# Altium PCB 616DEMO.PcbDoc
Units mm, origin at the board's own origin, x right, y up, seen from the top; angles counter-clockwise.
Board outline 70 x 50 mm, 2 copper layers (Top Layer, Bottom Layer), stack 0.527 mm thick; 70 components, 103 nets, 390 pads, 160 vias.
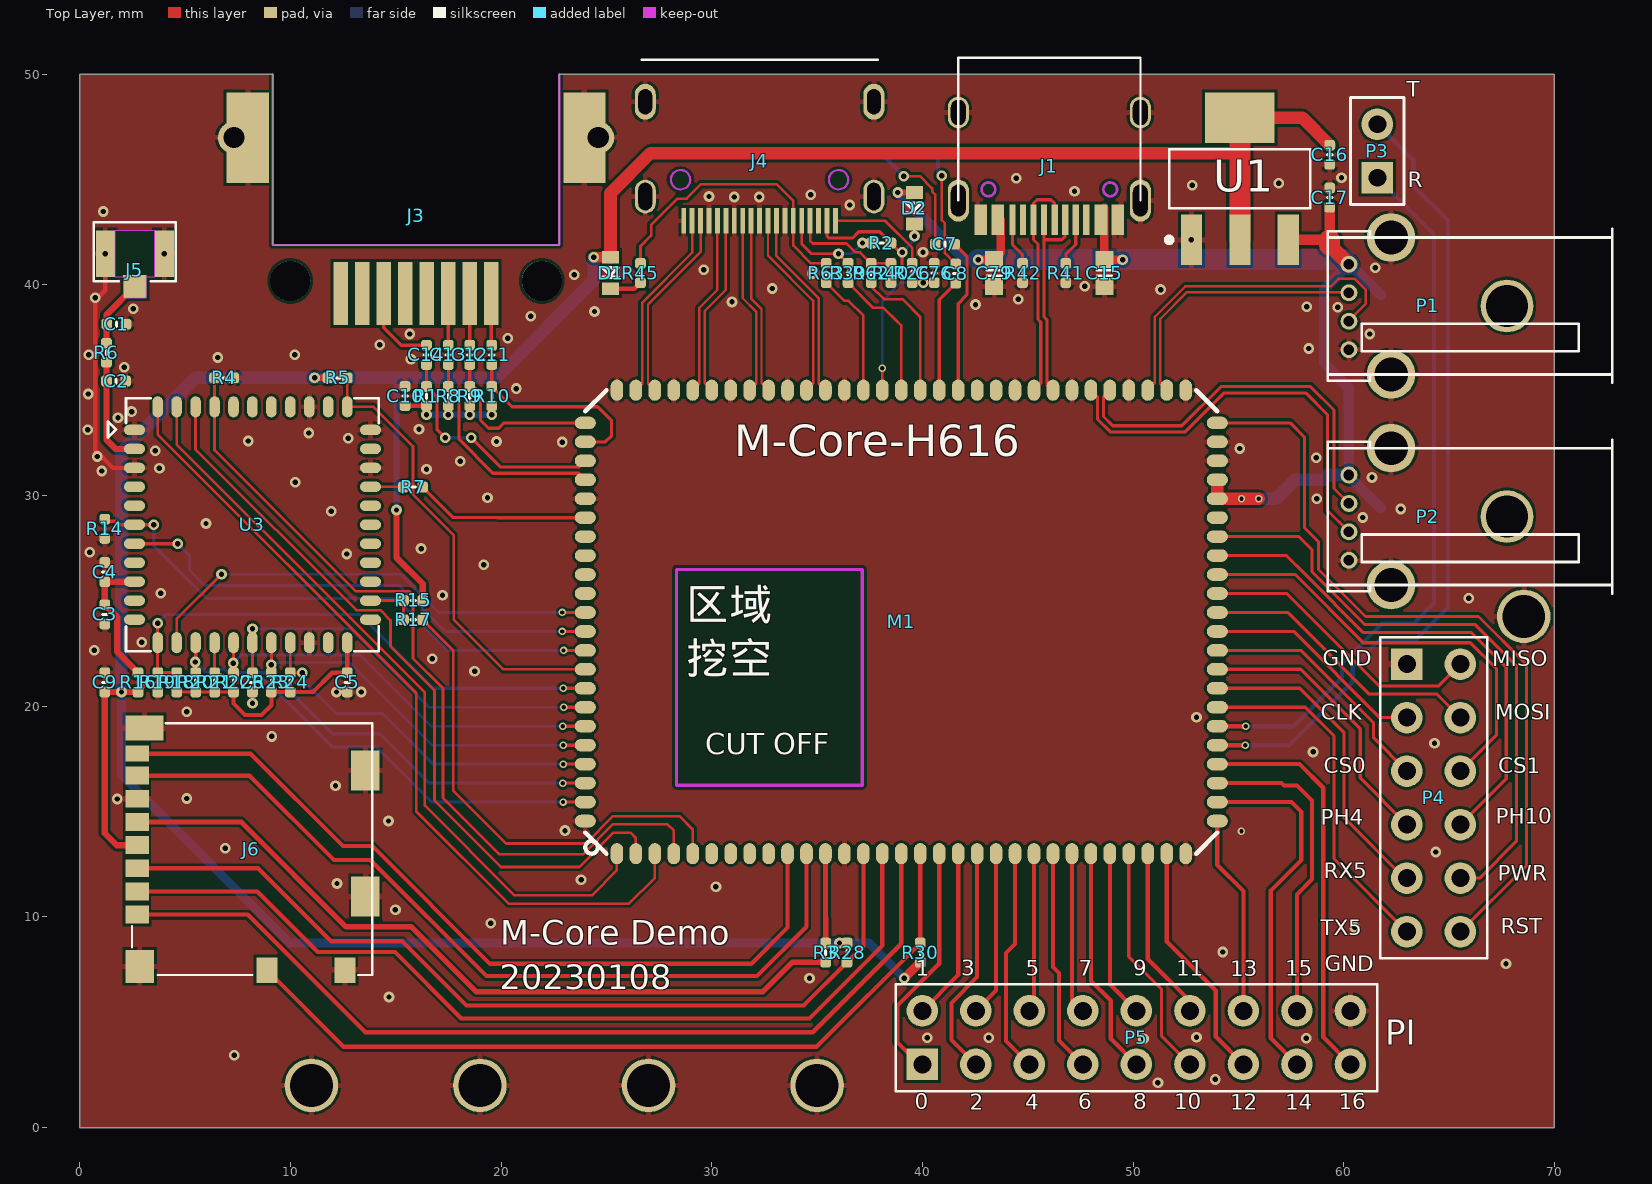
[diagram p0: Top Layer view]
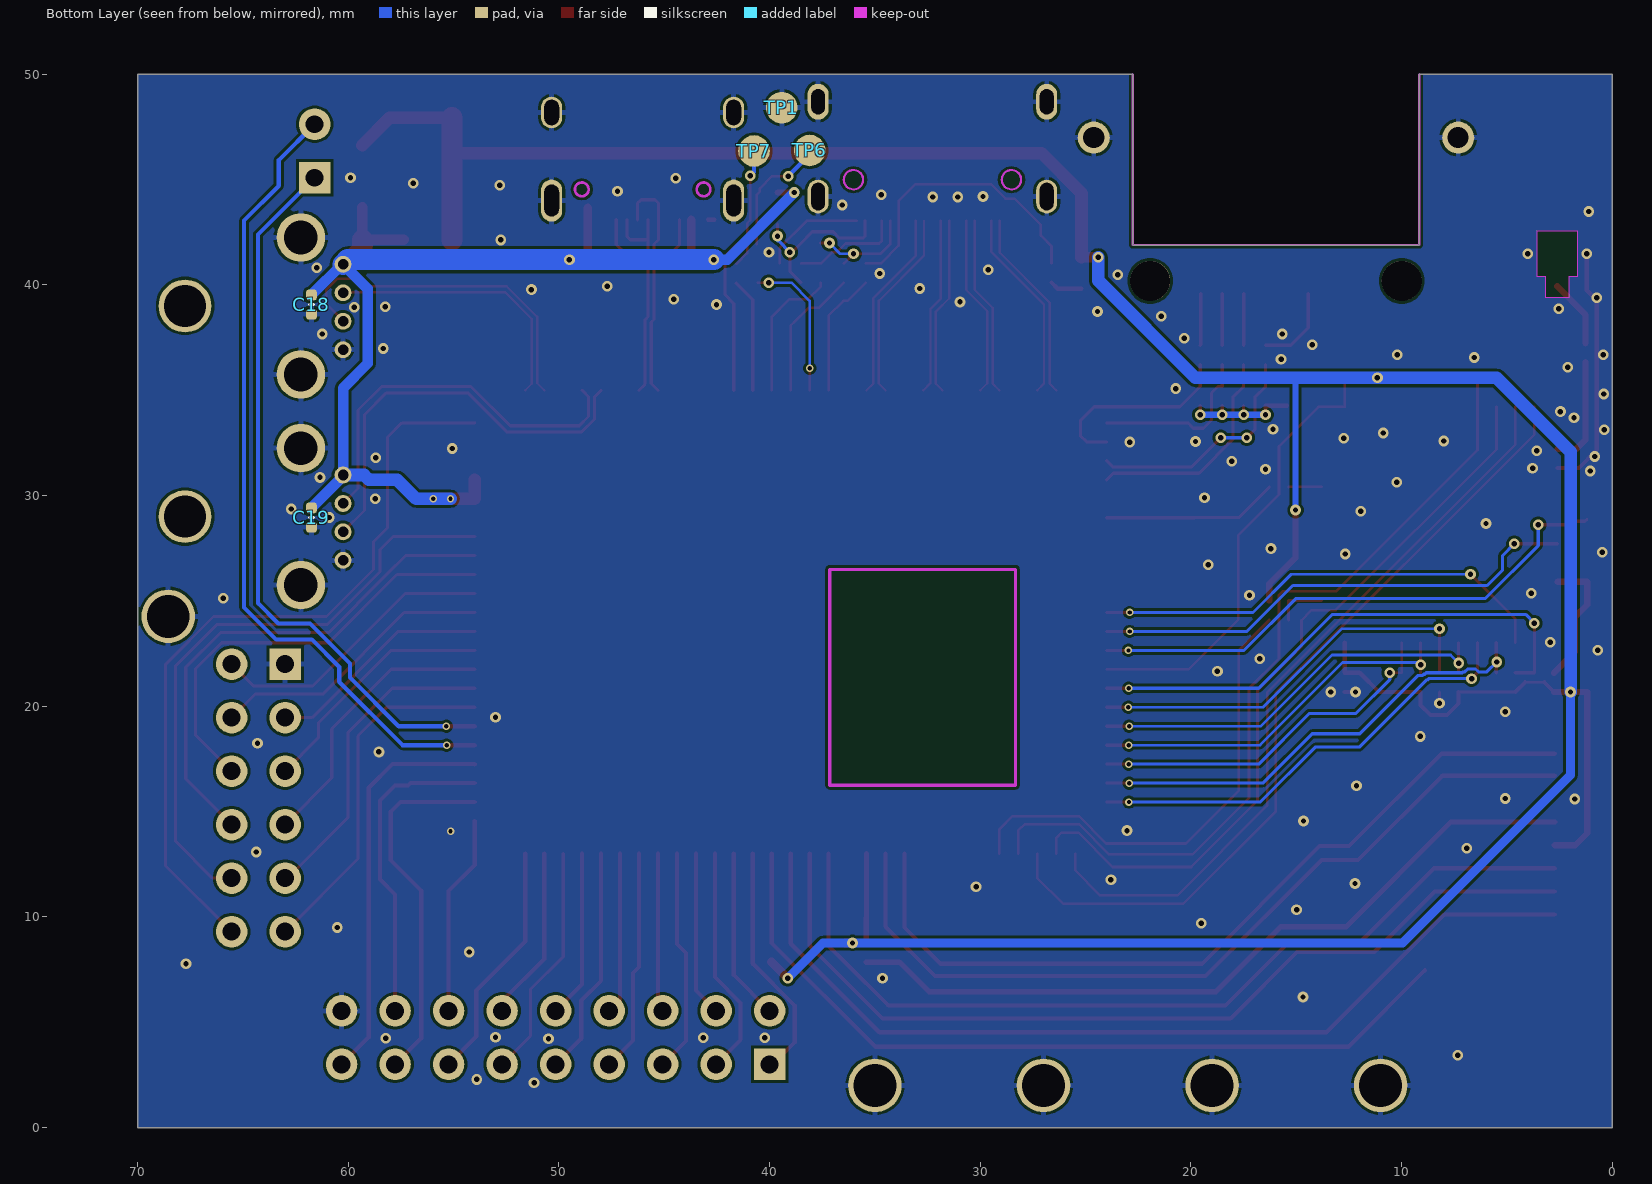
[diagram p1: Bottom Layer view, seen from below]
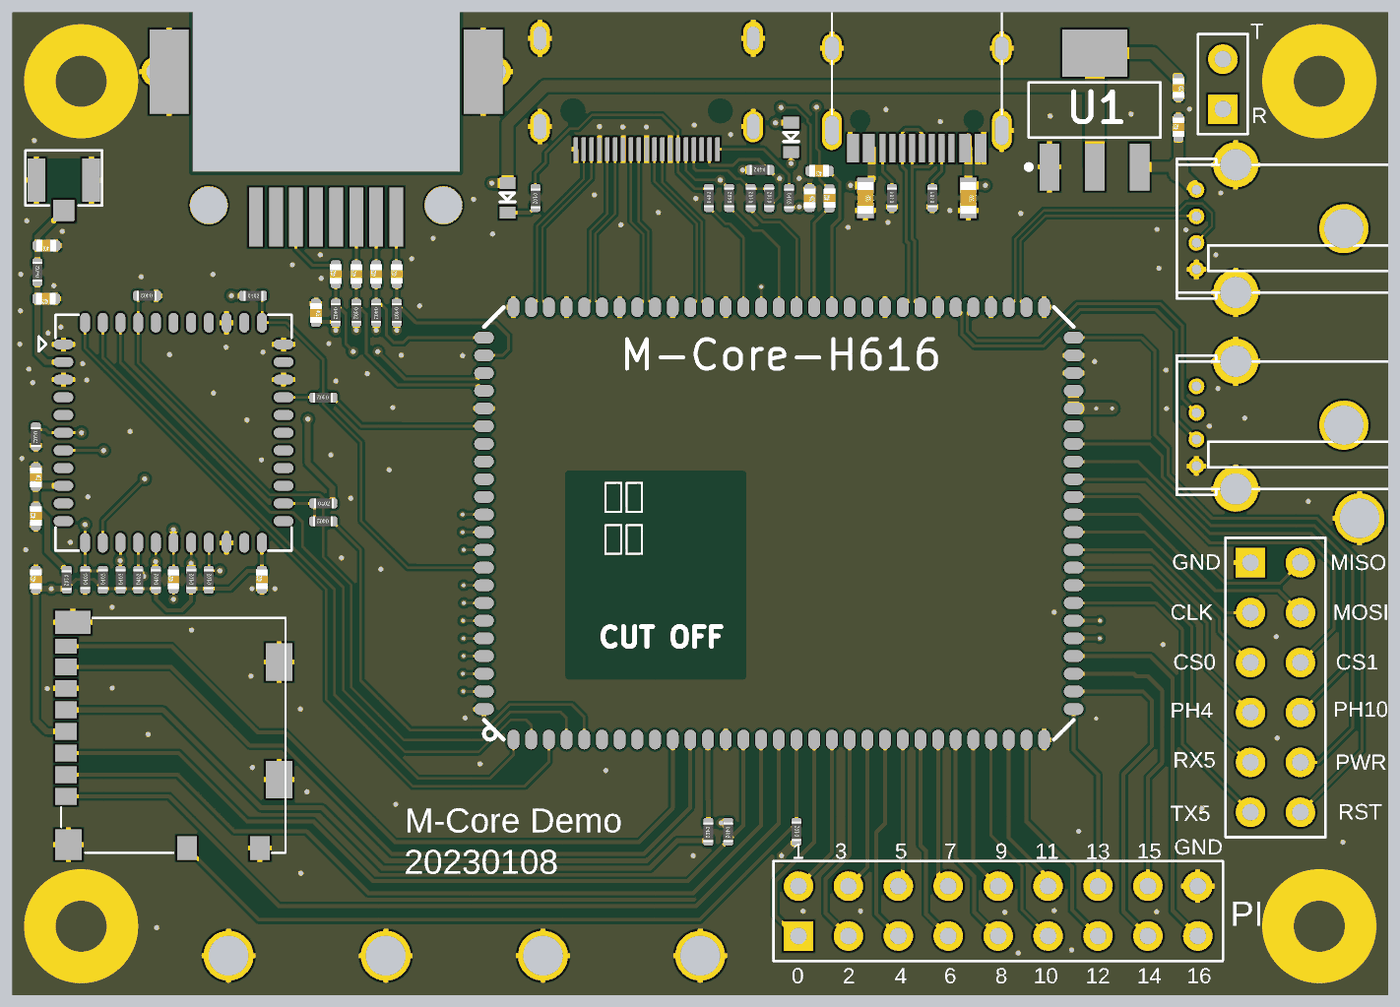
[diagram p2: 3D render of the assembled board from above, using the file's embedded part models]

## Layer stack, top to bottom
Top Solder: solder mask 0.0102, Solder Resist, Dk 3.5
Top Layer: signal copper 0.035
Dielectric2: prepreg 0.4572, PR-4, Dk 4.4
Bottom Layer: signal copper 0.035
Bottom Solder: solder mask 0.0102, Solder Resist, Dk 3.5

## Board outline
0,0 0,50 9.165,50 9.165,41.89 22.765,41.89 22.765,50 70.002,50 70.002,0

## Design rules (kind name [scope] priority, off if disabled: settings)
AssemblyTestPointUsage [All] p1 off:
AssemblyTestpoint [All] p1 off: testpointundercomponent=TRUE minsize=1.016 maxsize=2.54 preferedsize=1.524 minholesize=0 maxholesize=1.016 preferedholesize=0.813 testpointgrid=0.025 usegrid=TRUE gridtolerance=0 allowsidetop=TRUE allowsidebottom=TRUE
Clearance [All] p1: gap=0.127 ignorepadtopadclearanceinfootprint=FALSE
ComponentClearance [All] p1 off: gap=0.025 collisioncheckmode=3 verticalgap=0.025 showdistances=FALSE
DiffPairsRouting [All] p1: maxlimit=0.508 minlimit=0.14 mostfreqgap=0.178 toplayer_minwidth=0.102 toplayer_maxwidth=0.203 toplayer_prefwidth=0.117 bottomlayer_minwidth=0.102 bottomlayer_maxwidth=0.203 bottomlayer_prefwidth=0.117 maxuncoupledlength=76.2
FabricationTestPointUsage TestPointUsage [All] p1 off: valid=0 allowmultiple=FALSE
FabricationTestpoint Testpoint [(IsPad And (OnTopLayer Or OnBottomLayer))] p1 off: side=3 testpointundercomponent=TRUE minsize=1.016 maxsize=2.54 preferedsize=1.524 minholesize=0 maxholesize=1.016 preferedholesize=0.813 testpointgrid=0.025 allowsidetop=TRUE allowsidebottom=TRUE usegrid=TRUE gridtolerance=0
Height [All] p1 off: minheight=0 maxheight=25.4 prefheight=12.7
HoleSize [All] p1: absolutevalues=TRUE maxlimit=3.81 minlimit=0.025 maxpercent=80.000 minpercent=20.000
HoleToHoleClearance [All] p1: gap=0 allowstackedmicrovias=TRUE
MinimumSolderMaskSliver [All] p1 off: minsoldermaskwidth=0.025
NetAntennae [All] p1: netantennaetolerance=0.254
PlaneClearance [All] p1: clearance=0.127
PlaneConnect [All] p1: planeconnectstyle=Direct reliefexpansion=0.508 reliefentries=4 reliefconductorwidth=0.635 reliefairgap=0.254
PolygonConnect PolygonConnect_1 [All vs IsPad] p1: connectstyle=Relief reliefconductorwidth=0.254 reliefentries=4 polygonreliefangle="90 Angle" airgapwidth=0.127
PolygonConnect PolygonConnect_isvia [All vs IsVia] p2: connectstyle=Direct reliefconductorwidth=0.254 reliefentries=4 polygonreliefangle="90 Angle" airgapwidth=0.254
PolygonConnect [All] p3: connectstyle=Direct reliefconductorwidth=0.203 reliefentries=4 polygonreliefangle="90 Angle" airgapwidth=0.254
RoutingVias [All] p1: holewidth=0.203 width=0.406 viastyle="Through Hole" minholewidth=0.178 minwidth=0.356 maxholewidth=2.54 maxwidth=2.54
ShortCircuit [InNet('WIFI') vs InNet('GND')] p1 off: allowed=FALSE
SilkToSilkClearance [All] p1: silktosilkclearance=0
SilkToSolderMaskClearance SilkscreenOverComponentPads [IsPad] p1: minsilkscreentomaskgap=0 clearancetoexposedcopper=TRUE
SolderMaskExpansion [All] p1: expansion=0.102 istentingtop=FALSE
Width [All] p1: maxlimit=2.54 minlimit=0.12 preferedwidth=0.12
14 further rules are at their usual default settings.

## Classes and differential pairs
differential pair TXO: +TXO_P -TXO_N
differential pair RXI: +RXI_P -RXI_N
differential pair USB2: +USB2_P -USB2_N
differential pair USB1: +USB1_P -USB1_N
differential pair USB0: +USB0_P -USB0_N
differential pair HTXC: +HTXC_P -HTXC_N
differential pair HTX2: +HTX2_P -HTX2_N
differential pair HTX1: +HTX1_P -HTX1_N
differential pair HTX0: +HTX0_P -HTX0_N

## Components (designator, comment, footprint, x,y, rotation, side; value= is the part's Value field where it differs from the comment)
C1 "NC" C0402 1.742,38.137 r180 top
C2 "NC" C0402 1.727,35.433 r180 top
C3 "10uF" C0402 1.194,24.359 r90 top
C4 "0.1uF" C0402 1.194,26.365 r270 top
C5 "2.2uF" C0402 12.7,21.133 r90 top
C6 "NC" C0402 8.201,21.133 r90 top
C7 "10uF" C0402 41.072,41.935 r180 top
C8 "10uF" C0402 41.58,40.538 r90 top
C9 "0.1uF" C0402 1.194,21.133 r90 top
C10 "0.1uF" C0402 15.443,34.722 r270 top
C11 "0.1uF" C0402 19.558,36.678 r90 top
C12 "0.1uF" C0402 18.517,36.678 r90 top
C13 "0.1uF" C0402 17.501,36.678 r90 top
C14 "0.1uF" C0402 16.459,36.678 r90 top
C15 "47uF" C0603 48.641,40.564 r270 top
C16 "10uF" C0402 59.334,46.177 r270 top
C17 "10uF" C0402 59.334,44.145 r90 top
C18 "10uF" C0402 61.747,39.065 r270 bottom
C19 "10uF" C0402 61.747,28.956 r270 bottom
C76 "0.1uF" C0402 40.564,40.564 r270 top
C79 "47uF" C0603 43.409,40.564 r270 top
D1 "Diode" SOD523 25.197,40.564 r270 top
D2 "Diode" SOD523 39.624,43.637 r270 top
J1 "USB-TypeC-16P" USB-TYPEC-16P 46.027,45.636 r180 top locked
J3 "RJ45" RJ45 15.965,39.59 r180 top locked
J4 "HDMI_MINI" "HDMI_T _MINI" 32.273,43.043 r180 top locked
J5 "ipex" "I-PEX SOCKET" 2.616,41.478 r0 top
J6 "TF5033981892" TFCARD-1040310811 2.489,13.212 r270 top locked
M1 "MCore-H616" MCore-H616 39,24 r0 top locked
P1 "USB A RA STACKED" "USB-A STAND" 64,39 r270 top locked
P2 "USB A RA STACKED" "USB-A STAND" 64,29 r270 top locked
P3 "Header 2" HDR1X2 61.595,45.085 r90 top
P4 "Header 6X2" HDR2X6 63,22 r270 top locked
P5 "Header 9X2" HDR2X9 40,3 r0 top locked
R1 "50R" R0402 16.459,34.722 r270 top
R2 "1.8K" R0402 38.049,41.986 r180 top
R3 "33R" R0402 35.408,8.306 r270 top
R4 "NC/100K" R0402 6.858,35.585 r180 top
R5 "100K" R0402 12.243,35.585 r0 top
R6 "0R" R0402 1.27,36.779 r90 top
R7 "NC/0R" R0402 15.824,30.404 r180 top
R8 "50R" R0402 17.501,34.722 r270 top
R9 "50R" R0402 18.517,34.722 r270 top
R10 "50R" R0402 19.558,34.722 r270 top
R14 "NC/100K" R0402 1.194,28.423 r270 top
R15 "47K" R0402 15.824,25.019 r0 top
R16 "0R" R0402 2.769,21.133 r270 top
R17 "NC" R0402 15.824,24.105 r180 top
R18 "100K" R0402 4.607,21.133 r90 top
R19 "NC/100K" R0402 3.708,21.133 r90 top
R20 "47K" R0402 5.505,21.133 r90 top
R21 "47K" R0402 6.404,21.133 r90 top
R22 "47K" R0402 7.302,21.133 r90 top
R23 "47K" R0402 9.1,21.133 r90 top
R24 "47K" R0402 9.998,21.133 r90 top
R26 "1K" R0402 39.522,40.564 r270 top
R28 "10K" R0402 36.424,8.306 r270 top
R30 "10K" R0402 39.903,8.306 r90 top
R39 "100R" R0402 36.474,40.564 r90 top
R40 "1.8K" R0402 38.506,40.564 r90 top
R41 "5.1K" R0402 46.812,40.564 r90 top
R42 "5.1K" R0402 44.755,40.564 r90 top
R45 "27K 1%" R0402 26.619,40.564 r270 top
R62 "100R" R0402 37.567,40.564 r90 top
R63 "100R" R0402 35.433,40.564 r90 top
TP1 "TEST POINT" TEST-POINT1.5 39.421,48.412 r180 bottom
TP6 "TEST POINT" TEST-POINT1.5 38.1,46.38 r90 bottom
TP7 "TEST POINT" TEST-POINT1.5 40.742,46.355 r90 bottom
U1 "LM1117-3.3" SOT223-4N 55.067,45.034 r90 top
U3 "RTL8723DS" RTL8723DS 8.201,28.614 r0 top locked

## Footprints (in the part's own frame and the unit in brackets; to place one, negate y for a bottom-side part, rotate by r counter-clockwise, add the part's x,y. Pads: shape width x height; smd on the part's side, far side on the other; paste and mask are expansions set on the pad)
C0402 [mil]
  rrect50% 20x20 smd mask+2: 1(-18,0) 2(18,0)
  silkscreen extent 0,-4 0,4, body extent -19,-12 20,12, height 8
C0603 [mil]
  rect 31.5x33.46 smd: 1(-25,0) 2(25,0)
  silkscreen extent -5,-14 5,14, body extent -31,-16 32,16, height 12
"HDMI_T _MINI" [mm]
  rect 0.23x1.2 smd: 1(3.6,0) 2(3.2,0) 3(2.8,0) 4(2.4,0) 5(2,0) 6(1.6,0) 7(1.2,0) 8(0.8,0) 9(0.4,0) 10(0,0) 11(-0.4,0) 12(-0.8,0) 13(-1.2,0) 14(-1.6,0) 15(-2,0) 16(-2.4,0) 17(-2.8,0) 18(-3.2,0) 19(-3.6,0)
  oval 1x1.6 hole 0.65 slot 1.3 at 90 deg: 20(-5.425,-1.15) 23(5.425,-1.15)
  oval 1x1.7 hole 0.65 slot 1.2 at 90 deg: 21(-5.425,-5.65) 22(5.425,-5.65)
  Keep-Out Layer circle w0.1: c-3.75,-1.95 r0.46
  Keep-Out Layer circle w0.1: c3.75,-1.95 r0.46
  silkscreen extent -5.6,-7.65 5.6,-7.65
HDR1X2 [mm]
  rect 1.5x1.5 hole 0.85: 1(0,0)
  round 1.5 hole 0.85: 2(2.54,0)
  silkscreen extent -1.27,-1.27 3.81,1.27
HDR2X6 [mm]
  rect 1.5x1.5 hole 0.85: 1(0,0)
  round 1.5 hole 0.85: 2(0,2.54) 3(2.54,0) 4(2.54,2.54) 5(5.08,0) 6(5.08,2.54) 7(7.62,0) 8(7.62,2.54) 9(10.16,0) 10(10.16,2.54) 11(12.7,0) 12(12.7,2.54)
  silkscreen extent -1.27,-1.27 13.97,3.81
HDR2X9 [mm]
  rect 1.5x1.5 hole 0.85: 1(0,0)
  round 1.5 hole 0.85: 2(0,2.54) 3(2.54,0) 4(2.54,2.54) 5(5.08,0) 6(5.08,2.54) 7(7.62,0) 8(7.62,2.54) 9(10.16,0) 10(10.16,2.54) 11(12.7,0) 12(12.7,2.54) 13(15.24,0) 14(15.24,2.54) 15(17.78,0) 16(17.78,2.54) 17(20.32,0) 18(20.32,2.54)
  silkscreen extent -1.27,-1.27 21.59,3.81
"I-PEX SOCKET" [mm]
  rect 1.1x1.1 smd: 1(0,-1.55)
  rect 0.9x2.2 smd: 2(1.4,0) 3(-1.4,0)
  Keep-Out Layer pour cut-out: -0.95,1.1 -0.95,-1.101 -0.551,-1.101 -0.551,-2.101 0.001,-2.101 0.55,-2.101 0.55,-1.101 0.95,-1.101 0.95,1.1
  silkscreen extent -1.95,-1.3 1.95,1.5
MCore-H616 [mm]
  oval 0.6x1 smd mask+0.051: 1(-13.5,-11) 2(-12.6,-11) 3(-11.7,-11) 4(-10.8,-11) 5(-9.9,-11) 6(-9,-11) 7(-8.1,-11) 8(-7.2,-11) 9(-6.3,-11) 10(-5.4,-11) 11(-4.5,-11) 12(-3.6,-11) 13(-2.7,-11) 14(-1.8,-11) 15(-0.9,-11) 16(0,-11) 17(0.9,-11) 18(1.8,-11) 19(2.7,-11) 20(3.6,-11) 21(4.5,-11) 22(5.4,-11) 23(6.3,-11) 24(7.2,-11) 25(8.1,-11) 26(9,-11) 27(9.9,-11) 28(10.8,-11) 29(11.7,-11) 30(12.6,-11) 31(13.5,-11) 54(13.5,11) 55(12.6,11) 56(11.7,11) 57(10.8,11) 58(9.9,11) 59(9,11) 60(8.1,11) 61(7.2,11) 62(6.3,11) 63(5.4,11) 64(4.5,11) 65(3.6,11) 66(2.7,11) 67(1.8,11) 68(0.9,11) 69(0,11) 70(-0.9,11) 71(-1.8,11) 72(-2.7,11) 73(-3.6,11) 74(-4.5,11) 75(-5.4,11) 76(-6.3,11) 77(-7.2,11) 78(-8.1,11) 79(-9,11) 80(-9.9,11) 81(-10.8,11) 82(-11.7,11) 83(-12.6,11) 84(-13.5,11)
  oval 1x0.6 smd mask+0.051: 32(15,-9.45) 33(15,-8.55) 34(15,-7.65) 35(15,-6.75) 36(15,-5.85) 37(15,-4.95) 38(15,-4.05) 39(15,-3.15) 40(15,-2.25) 41(15,-1.35) 42(15,-0.45) 43(15,0.45) 44(15,1.35) 45(15,2.25) 46(15,3.15) 47(15,4.05) 48(15,4.95) 49(15,5.85) 50(15,6.75) 51(15,7.65) 52(15,8.55) 53(15,9.45) 85(-15,9.45) 86(-15,8.55) 87(-15,7.65) 88(-15,6.75) 89(-15,5.85) 90(-15,4.95) 91(-15,4.05) 92(-15,3.15) 93(-15,2.25) 94(-15,1.35) 95(-15,0.45) 96(-15,-0.45) 97(-15,-1.35) 98(-15,-2.25) 99(-15,-3.15) 100(-15,-4.05) 101(-15,-4.95) 102(-15,-5.85) 103(-15,-6.75) 104(-15,-7.65) 105(-15,-8.55) 106(-15,-9.45)
  Keep-Out Layer lines w0.152: -10.668,-7.747 -10.668,2.489 -1.854,2.489 -1.854,-7.747 -10.668,-7.747
  silkscreen extent -15,-11 15,11
R0402 [mil]
  rrect50% 20x20 smd mask+2: 1(-18,0) 2(18,0)
  silkscreen extent -4,0 4,0, body extent -19,-10 21,10, height 14
RJ45 [mm] "RJ45接口不带变压器H8.6"
  rect 0.7x3 smd: 1(-3.57,0) 2(-2.55,0) 3(-1.53,0) 4(-0.51,0) 5(0.51,0) 6(1.53,0) 7(2.55,0) 8(3.57,0)
  round 1.524 hole 1: 9(-8.65,-7.4) 10(8.65,-7.4)
  rect 2x4.3 smd: 9(-7.99,-7.4) 10(7.99,-7.4)
  round 1.9 hole 1.9: ""(-5.97,-0.6) ""(5.97,-0.6)
  Keep-Out Layer lines w0.1: 6.8,-10.4 6.8,-2.3 -6.8,-2.3 -6.8,-10.4
RTL8723DS [mm]
  oval 1x0.5 smd: 1(-5.6,4.5) 2(-5.6,3.6) 3(-5.6,2.7) 4(-5.6,1.8) 5(-5.6,0.9) 6(-5.6,0) 7(-5.6,-0.9) 8(-5.6,-1.8) 9(-5.6,-2.7) 10(-5.6,-3.6) 11(-5.6,-4.5) 23(5.6,-4.5) 24(5.6,-3.6) 25(5.6,-2.7) 26(5.6,-1.8) 27(5.6,-0.9) 28(5.6,0) 29(5.6,0.9) 30(5.6,1.8) 31(5.6,2.7) 32(5.6,3.6) 33(5.6,4.5)
  oval 0.5x1 smd: 12(-4.5,-5.6) 13(-3.6,-5.6) 14(-2.7,-5.6) 15(-1.8,-5.6) 16(-0.9,-5.6) 17(0,-5.6) 18(0.9,-5.6) 19(1.8,-5.6) 20(2.7,-5.6) 21(3.6,-5.6) 22(4.5,-5.6) 34(4.5,5.6) 35(3.6,5.6) 36(2.7,5.6) 37(1.8,5.6) 38(0.9,5.6) 39(0,5.6) 40(-0.9,5.6) 41(-1.8,5.6) 42(-2.7,5.6) 43(-3.6,5.6) 44(-4.5,5.6)
  silkscreen extent -6.86,-6 6,6, body extent -6,-6 6,6, height 1.6
SOD523 [mm]
  rect 0.6x0.8 smd: A(-0.75,0) K(0.75,0)
  silkscreen extent -0.25,-0.38 0.2,0.38
SOT223-4N [mm] "SOT223, 4-Leads, Body 6.5x3.5mm, Pitch 2.3mm, Lead Span 7mm, IPC Medium Density"
  rect 2.4x1 smd: 1(-2.9,2.3) 2(-2.9,0) 3(-2.9,-2.3)
  rect 2.4x3.3 smd: 4(2.9,0)
  silkscreen extent -3.02,-3.35 1.4,3.47, body extent -1.85,-3.35 1.85,3.35, height 1.7
TEST-POINT1.5 [mm]
  round 1.5 smd paste-0.4: 1(0,0)
TFCARD-1040310811 [mm] "TFCARD"
  rect 0.85x1.1 smd: 1(3.105,0.239) 2(2.005,0.239) 3(0.905,0.239) 4(-0.195,0.239) 5(-1.295,0.239) 6(-2.395,0.239) 7(-3.495,0.239)
  rect 0.75x1.1 smd: 8(-4.545,0.239)
  rect 1.55x1.35 smd: G1(5.565,0.365)
  rect 1.17x1.8 smd: G2(-5.755,0.59)
  rect 1.9x1.35 smd: G3(-3.73,11.075) G4(2.24,11.075)
  rect 1.2x1 smd: G5(5.74,10.1) G6(5.74,6.4)
  silkscreen extent -5.98,0 5.98,11.4
"USB-A STAND" [mm]
  round 0.8 hole 0.5: 1(-1.975,-3.75) 2(-0.625,-3.75) 3(0.725,-3.75) 4(2.075,-3.75)
  round 2.3 hole 1.6: 5(-3.25,-1.75) 6(3.25,-1.75)
  round 2.5 hole 2: 7(0,3.75)
  silkscreen extent -3.65,-4.75 3.65,8.75
USB-TYPEC-16P [mm]
  oval 1x1.5 hole 0.7 slot 1.2 at 90 deg: 0(-4.32,-2.548) 0(4.32,-2.548)
  oval 1x2 hole 0.7 slot 1.5 at 90 deg: 0(-4.32,1.632) 0(4.32,1.632)
  rect 0.3x1.45 smd: A1(-3.4,2.548) A4(-2.6,2.548) A5(-1.25,2.548) A6(-0.25,2.548) A7(0.25,2.548) A8(1.25,2.548) A9(2.6,2.548) A12(3.4,2.548) B1(3.1,2.548) B4(2.3,2.547) B5(1.75,2.548) B6(0.75,2.547) B7(-0.75,2.547) B8(-1.75,2.548) B9(-2.3,2.547) B12(-3.1,2.548)
  Keep-Out Layer circle w0.127: c2.89,1.103 r0.325
  Keep-Out Layer circle w0.127: c-2.89,1.103 r0.325
  silkscreen extent -4.33,-5.15 4.33,1.63

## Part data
C1 C2 C3 C4 C5 C6 C7 C8 C9 C10 C11 C12 C13 C14 C15 C16 C17 C18 C19 C76 C79: library part CAP, "普通小电容"
D1 D2: "普通二极管"
J3: "RJ45不带网络变压器"
J5: library part MCX_IPEX
P1 P2: library part "USB A Right Angle Stacked", "CONN RECEPT STACKED USB A RT ANG"
P3: "Header, 2-Pin"
P4: "Header, 6-Pin, Dual row"
P5: "Header, 9-Pin, Dual row"
R1 R2 R3 R4 R5 R6 R7 R8 R9 R10 R14 R15 R16 R17 R18 R19 R20 R21 R22 R23 R24 R26 R28 R30 R39 R40 R41 R42 R45 R62 R63: library part RES, "普通电阻"
TP1 TP6 TP7: library part TP, "Description"
U1: "800mA and 1A Low Dropout Positive Regulator 2.85V, 3.3V, 5V, and Adjustable", PackageDocument=revC
U3: library part AP6212

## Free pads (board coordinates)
  round 2.54 hole 2.032: 2(11,2) 2(27,2) 2(35,2) 2(68.547,24.264) ""(19,2)

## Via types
v1: diameter 0.508, hole 0.254, Top Layer to Bottom Layer, tented both sides, 144 vias
v2: diameter 0.356, hole 0.203, Top Layer to Bottom Layer, tented both sides, 16 vias

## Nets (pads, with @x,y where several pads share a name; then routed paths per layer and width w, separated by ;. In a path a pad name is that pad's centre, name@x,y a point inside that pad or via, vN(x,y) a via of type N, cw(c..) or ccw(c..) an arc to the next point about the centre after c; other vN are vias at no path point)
AP-CLK24M-OUT: M1.90 R7.1 | length 8.3
  Top Layer w0.152: R7.1 17.733,28.952 19.812,28.952 19.814,28.95 M1.90
AP-SDC1-CLK: C6.2 M1.100 U3.17 | length 19.4
  Top Layer w0.127: C6.2 U3.17 v1(8.201,23.676)
  Top Layer w0.15: v2(22.973,19.95) M1.100
  Bottom Layer w0.127: v1(8.201,23.676) 12.849,23.676 16.573,19.952 v2@22.958,19.952
AP-SDC1-CMD: M1.101 R22.2 U3.16 | length 19.7
  Top Layer w0.127: U3.16 7.301,21.592 R22.2
  Top Layer w0.15: v2(22.936,19.05) M1.101
  Bottom Layer w0.127: v1(7.29,22.047) 7.671,22.428 13.31,22.428 16.686,19.052 v2@22.958,19.052
AP-SDC1-D0: M1.102 R23.2 U3.18 | length 18
  Top Layer w0.127: R23.2 9.101,21.591 U3.18
  Top Layer w0.15: v2(22.951,18.15) M1.102
  Bottom Layer w0.127: v1(9.093,21.971) 9.195,22.073 12.802,22.073 16.722,18.152 v2@22.958,18.152
AP-SDC1-D1: M1.103 R24.2 U3.19 | length 17.4
  Top Layer w0.127: U3.19 10.001,21.593 v1(10.564,21.593)
  Top Layer w0.15: v2(22.958,17.25) M1.103
  Bottom Layer w0.15: v1(10.564,21.593) 10.564,21.263 12.167,19.66 14.376,19.66 16.784,17.252 v2(22.958,17.25)
AP-SDC1-D2: M1.104 R20.2 U3.14 | length 22.5
  Top Layer w0.15: U3.14 5.505,23.009 R20.2 ; v2(22.929,16.35) M1.104
  Bottom Layer w0.15: v1(5.486,22.098) 5.956,21.628 6.353,21.628 6.491,21.767 6.869,21.767 7.008,21.628 7.074,21.628 7.114,21.588 8.832,21.588 8.904,21.515 8.95,21.515 9.002,21.463 9.22,21.463 11.989,18.694 14.249,18.694 16.592,16.352 v2@22.958,16.352
AP-SDC1-D3: M1.105 R21.2 U3.15 | length 21.6
  Top Layer w0.15: U3.15 6.401,21.593 R21.2 6.404,21.587 v1(6.68,21.311) ; v2(22.943,15.45) M1.105
  Bottom Layer w0.15: v1(6.68,21.311) 8.717,21.311 8.79,21.238 8.836,21.238 12.014,18.059 14.097,18.059 16.705,15.452 v2@22.958,15.452
AP-UART1-CTS: M1.4 R4.2 U3.41 | length 39.8
  Top Layer w0.127: R4.2 U3.41 6.401,32.156 13.106,25.451 13.365,25.451 13.368,25.454 14.233,25.454 14.237,25.451 15.096,25.451 15.108,25.464 15.626,25.464 15.638,25.451 15.646,25.451 15.824,25.273 15.824,22.276 17.247,20.853 17.247,15.646 19.926,12.967 23.889,12.967 25.324,14.402 27.889,14.402 28.2,14.091 M1.4
AP-UART1-RTS: M1.3 U3.44 | length 39.1
  Top Layer w0.127: U3.44 3.701,32.901 15.977,20.625 15.977,15.011 20.371,10.617 26.06,10.617 27.3,11.857 M1.3
AP-UART1-RX: M1.2 U3.42 | length 36.4
  Top Layer w0.127: U3.42 5.501,32.193 13.132,24.562 14.275,24.562 14.757,24.079 14.757,22.835 16.84,20.752 16.84,15.519 19.99,12.37 23.724,12.37 25.349,13.995 26.137,13.995 26.4,13.732 M1.2
AP-UART1-TX: M1.1 U3.43 | length 36
  Top Layer w0.127: U3.43 4.601,32.432 12.827,24.206 16.383,20.65 16.383,15.291 20.65,11.024 24.308,11.024 25.5,12.216 M1.1
AP-WAKE-BT: M1.97 R14.1 U3.6 | length 25.9
  Top Layer w0.15: R14.1 1.295,28.778 1.676,28.778 1.841,28.614 U3.6 v1(3.517,28.614) ; v2(22.968,22.65) M1.97
  Bottom Layer w0.15: v1(3.517,28.614) 3.517,27.623 6.02,25.121 15.011,25.121 17.48,22.652 v2@22.911,22.652
BT-RESETN: M1.98 R5.2 U3.34 | length 21.5
  Top Layer w0.12: 20.537,21.752 20.538,21.75 M1.98
  Top Layer w0.127: U3.34@12.7,34.215 R5.2 ; U3.34 13.945,34.214 15.824,32.334 15.824,30.048 17.755,28.118 17.755,24.115 20.118,21.752 20.537,21.752
BT-WAKE-AP: M1.96 U3.7 | length 23.5
  Top Layer w0.15: U3.7 4.646,27.714 v1(4.648,27.711) ; v2(22.911,23.55) M1.96
  Bottom Layer w0.15: v1(4.648,27.711) 5.207,27.153 5.207,26.467 5.944,25.73 15.164,25.73 17.342,23.552 v2@22.911,23.552
CLK-FANOUT1: M1.5 R17.1 | length 23.1
  Top Layer w0.127: R17.1 17.729,22.657 17.729,16.002 20.244,13.487 24.028,13.487 25.324,14.783 28.473,14.783 29.1,14.156 M1.5
GND: C1.1 C2.1 C3.1 C4.1 C5.1 C6.1 C9.2 C10.1 C15.2 C16.2 C17.2 C18.2 C19.2 C76.1 C79.2 J1.0 J1.A1 J1.A12 J1.B1 J1.B12 J3.9 J3.10 J4.1 J4.4 J4.7 J4.10 J4.13 J4.20 J4.21 J4.22 J4.23 J5.2 J5.3 J6.6 J6.G1 J6.G2 J6.G3 J6.G4 J6.G5 M1.13 M1.31 M1.51 M1.52 M1.54 M1.57 M1.60 M1.63 M1.72 M1.75 M1.78 M1.81 M1.84 M1.89 M1.106 P1.4 P1.5 P1.6 P2.4 P2.5 P2.6 P4.1 P5.18 pad. pad.2 R4.1 R14.2 R19.1 R41.1 R42.1 TP1.1 U1.1 U3.1 U3.3 U3.20 U3.31 U3.33 U3.36 | length 13.1
  Top Layer w0.127: v1(8.201,20.139) C6.1
  Top Layer w0.2: v1(1.216,41.478) 1.216,39.748 0.737,39.268 0.737,32.156 1.579,31.314 U3.3 ; v1(12.192,20.676) C5.1 ; J1.A12 J1.B1
  other v1: 51.181,2.134 53.899,2.286 7.341,3.429 50.495,4.216 58.228,4.235 40.234,4.267 43.155,4.267 53.01,4.293 14.681,6.198 34.646,7.087 67.703,7.776 54.254,8.331 60.528,9.5 19.507,9.703 14.986,10.338 30.201,11.43 12.217,11.582 23.8,11.76 64.364,13.081 6.909,13.259 23.038,14.097 14.656,14.554 1.778,15.596 5.08,15.621 12.141,16.231 58.547,17.831 64.313,18.237 9.119,18.567 53.01,19.482 5.08,19.736 13.36,20.676 18.745,21.666 16.739,22.25 0.686,22.657 2.946,23.038 65.938,25.121 17.221,25.273 3.849,25.357 19.177,26.721 12.675,27.229 0.483,27.305 16.205,27.483 5.994,28.677 60.909,28.956 11.938,29.261 62.713,29.362 58.725,29.845 19.355,29.896 10.236,30.632 61.341,30.861 1.041,31.166 16.459,31.242 3.785,31.293 18.059,31.623 58.699,31.801 0.838,31.852 3.581,32.131 55.067,32.233 22.911,32.537 19.787,32.563 8.001,32.588 12.751,32.715 10.871,32.969 0.381,33.122 16.104,33.147 1.82,33.688 2.464,33.985 0.406,34.823 20.726,35.077 2.108,36.093 15.723,36.474 6.553,36.551 0.432,36.678 10.211,36.678 58.344,36.982 14.249,37.16 20.32,37.465 15.672,37.668 61.239,37.668 21.412,38.506 24.435,38.735 2.54,38.862 59.715,38.938 58.242,38.964 42.52,39.065 30.963,39.192 44.552,39.319 0.737,39.395 51.308,39.776 32.868,39.827 47.701,39.929 23.47,40.488 34.773,40.538 29.616,40.716 61.493,40.818 4.016,41.478 40.03,41.554 52.767,42.134 1.118,43.485 36.551,43.79 31.064,44.171 32.258,44.171 29.87,44.196 34.696,44.272 47.219,44.45 52.807,44.729 56.921,44.831 44.45,45.06 59.893,45.085
  other v2: 55.143,14.072
H5V: D2.K J4.18 R2.1 R40.1 | length 8.1
  Top Layer w0.15: J4.18 35.473,42.302 35.548,42.226 36.689,42.226 36.982,42.52 37.973,42.52 R2.1 38.938,41.554 v1(39.04,41.554) 39.04,40.64 R40.1 ; v1(39.624,42.316) D2.K
  Bottom Layer w0.15: v1(39.04,41.554) 39.573,42.088 39.624,42.088 v1(39.624,42.316)
HCEC: M1.71 R63.1 | length 6
  Top Layer w0.12: M1.71 37.2,38.044
  Top Layer w0.127: R63.1 36.297,39.243 36.5,39.243 37.2,38.543 37.2,38.044
HDCEC: J4.14 R45.1 R63.2 | length 13.9
  Top Layer w0.127: R45.1 26.619,41.834 27.127,42.342 27.127,42.85 28.372,44.094 28.804,44.094 29.489,44.78 33.071,44.78 33.873,43.978 J4.14 33.873,41.87 34.722,41.021 R63.2
HDSCL: J4.15 R2.2 R39.2 | length 5.5
  Top Layer w0.127: J4.15 34.273,41.953 34.747,41.478 v1(36.017,41.478) R39.2 ; v1(37.16,41.986) R2.2
  Bottom Layer w0.127: v1(36.017,41.478) 36.652,41.478 v1(37.16,41.986)
HDSDA: J4.16 R40.2 R62.2 | length 5.2
  Top Layer w0.127: J4.16 34.673,42.086 34.798,41.961 36.398,41.961 36.817,41.542 37.046,41.542 R62.2 R40.2
HHPD: C76.2 M1.70 R26.2 | length 7.6
  Top Layer w0.127: M1.70 v2(38.1,36.043) ; R26.2 v1(40.043,40.107) C76.2
  Bottom Layer w0.127: v2(38.1,36.043) 38.1,39.243 38.964,40.107 v1(40.043,40.107)
HSCL: M1.69 R39.1 | length 6.4
  Top Layer w0.12: 38.837,38.227 39,38.064 M1.69
  Top Layer w0.127: R39.1 37.668,38.913 38.151,38.913 38.837,38.227
HSDA: M1.68 R62.1 | length 6.6
  Top Layer w0.127: R62.1 37.567,39.929 38.176,39.319 39.065,39.319 39.9,38.484 M1.68
HTX0_N: J4.9 M1.76 | length 8.4
  Top Layer w0.114: J4.9 31.873,39.349 32.362,38.86 32.362,35.338 M1.76
HTX0_P: J4.8 M1.77 | length 8.4
  Top Layer w0.114: J4.8 31.473,39.368 32.108,38.733 32.108,35.308 M1.77
HTX1_N: J4.6 M1.79 | length 8.6
  Top Layer w0.114: M1.79 29.667,35.333 29.667,38.76 30.673,39.766 J4.6
HTX1_P: J4.5 M1.80 | length 8.5
  Top Layer w0.114: M1.80 29.413,35.313 29.413,38.913 30.273,39.772 J4.5
HTX2_N: J4.3 M1.82 | length 9.2
  Top Layer w0.114: M1.82 26.975,35.325 26.975,39.065 29.473,41.563 J4.3
HTX2_P: J4.2 M1.83 | length 9.1
  Top Layer w0.114: M1.83 26.695,35.295 26.695,39.145 29.073,41.522 J4.2
HTXC_N: J4.12 M1.73 | length 9
  Top Layer w0.114: J4.12 33.073,41.375 35.077,39.37 35.077,35.323 M1.73
HTXC_P: J4.11 M1.74 | length 9.1
  Top Layer w0.114: J4.11 32.673,41.394 34.823,39.243 34.823,35.323 M1.74
LO: C7.1 M1.66 | length 7.3
  Top Layer w0.152: C7.1 42.113,41.351 42.113,39.522 41.7,39.109 41.7,38.044 M1.66
LRADC: M1.64
NetC1_2: C1.2 J5.1 R6.2 | length 3.2
  Top Layer w0.3: R6.2 1.27,38.582 J5.1
NetC2_2: C2.2 R6.1 U3.2 | length 5.2
  Top Layer w0.3: R6.1 C2.2 1.27,32.646 1.702,32.214 U3.2
NetC7_2: C7.2 TP6.1 | length 5.9
  Top Layer w0.12: v1(39.116,45.161) 39.878,45.161 40.462,44.577 40.462,44.425 40.615,44.272 C7.2
  Bottom Layer w0.2: TP6.1 38.1,46.177 v1(39.116,45.161)
NetC8_2: C8.2 TP7.1 | length 5.7
  Top Layer w0.12: v1(40.919,45.187) 40.919,43.078 41.072,42.926 41.072,41.504 C8.2
  Bottom Layer w0.2: TP7.1 40.742,45.364 v1(40.919,45.187)
NetC10_2: C10.2 R1.2 R8.2 R9.2 R10.2 | length 5.8
  Top Layer w0.15: v1(17.501,33.833) R8.2 ; v1(18.517,33.833) R9.2 ; v1(19.558,33.833) R10.2
  Top Layer w0.2: C10.2 R1.2 v1(16.459,33.833)
  Bottom Layer w0.3: v1(16.459,33.833) v1(17.501,33.833) v1(18.517,33.833) v1(19.558,33.833)
NetD1_K: D1.K R45.2 | length 1.5
  Top Layer w0.2: D1.K 26.326,39.814 R45.2
NetJ1_A5: J1.A5 R41.2 | length 2.3
  Top Layer w0.152: R41.2 46.812,41.453 47.277,41.917 J1.A5
NetJ1_B5: J1.B5 R42.2 | length 2.3
  Top Layer w0.15: J1.B5 44.277,41.905 44.755,41.427 R42.2
NetJ4_19: J4.19 R26.1 | length 4.9
  Top Layer w0.127: J4.19 38.237,43.043 39.522,41.758 R26.1
NetM1_12: M1.12 R3.1 | length 4.2
  Top Layer w0.254: M1.12@35.4,13 35.4,9.956 35.408,9.948 R3.1
NetR7_2: R7.2 U3.30 | length 1.6
  Top Layer w0.127: U3.30 15.357,30.414 R7.2
NetR15_1: R15.1 R17.2 U3.24 | length 2.5
  Top Layer w0.152: U3.24 15.362,25.014 R15.1 R17.2
PH4: M1.40 P4.7 | length 13.4
  Top Layer w0.15: M1.40 54.002,21.752 57.953,21.752 60.782,18.923 60.782,16.598 P4.7
PH10: M1.46 P4.8 | length 24.3
  Top Layer w0.15: M1.46 54.002,27.152 57.278,27.152 58.217,26.213 60.935,23.495 66.065,23.495 67.716,21.844 67.716,16.556 P4.8
PI0: M1.18 P5.1 | length 11.5
  Top Layer w0.2: P5.1@40.03,2.819 38.811,4.039 38.811,5.791 40.8,7.78 M1.18@40.8,13
PI1: M1.19 P5.2 | length 8.2
  Top Layer w0.2: P5.2 41.7,7.24 M1.19@41.7,13
PI2: M1.20 P5.3 | length 11
  Top Layer w0.2: P5.3 41.377,4.163 41.377,5.918 42.6,7.142 M1.20@42.6,13
PI3: M1.21 P5.4 | length 8
  Top Layer w0.2: P5.4 43.5,6.5 M1.21@43.5,13 ; P5.4@42.57,5.359 P5.4@42.645,5.434
PI4: M1.22 P5.5 | length 10.6
  Top Layer w0.2: M1.22@44.4,13 44.4,8.713 43.967,8.28 43.967,4.113 P5.5
PI5: M1.23 P5.6 | length 7.6
  Top Layer w0.2: P5.6 45.3,5.76 M1.23@45.3,13
PI6: M1.24 P5.7 | length 10.6
  Top Layer w0.2: M1.24@46.2,13 46.2,7.623 46.482,7.341 46.482,4.138 P5.7
PI7: M1.25 P5.8 | length 7.7
  Top Layer w0.2: M1.25@47.1,13 47.1,6.06 P5.8
PI8: M1.26 P5.9 | length 10.9
  Top Layer w0.2: M1.26@48,13 48,6.966 48.946,6.02 48.946,4.214 P5.9
PI9: M1.27 P5.10 | length 8
  Top Layer w0.2: M1.27@48.9,13 48.9,6.8 P5.10
PI10: M1.28 P5.11 | length 11.2
  Top Layer w0.15: M1.28@49.8,13 49.8,8.112 51.359,6.553 51.359,4.341 P5.11
PI11: M1.29 P5.12 | length 8.3
  Top Layer w0.2: M1.29@50.7,13 50.7,7.999 52.7,5.999 P5.12
PI12: M1.30 P5.13 | length 11.5
  Top Layer w0.2: M1.30@51.6,13 51.6,8.827 53.924,6.502 53.924,4.316 P5.13
PI13: M1.32 P5.14 | length 9.5
  Top Layer w0.2: M1.32 54,12.467 55.24,11.227 P5.14
PI14: M1.33 P5.15 | length 17.3
  Top Layer w0.2: M1.33 54.002,15.452 57.522,15.452 57.988,14.986 57.988,12.7 56.54,11.252 56.54,4.24 P5.15
PI15: M1.34 P5.16 | length 15.1
  Top Layer w0.2: M1.34 54.002,16.352 57.045,16.352 57.166,16.231 57.785,16.231 58.496,15.519 58.496,11.786 57.78,11.069 P5.16
PI16: M1.35 P5.17 | length 19.2
  Top Layer w0.2: M1.35 M1.35 57.907,17.252 59.03,16.129 59.03,4.29 P5.17
PWRON: M1.47 P4.10 | length 29.1
  Top Layer w0.15: M1.47 M1.47 57.876,28.052 58.496,27.432 58.496,26.391 61.011,23.876 66.243,23.876 68.199,21.92 68.199,13.589 66.45,11.84 P4.10
RESET: M1.53 P4.12 | length 36.7
  Top Layer w0.15: M1.53 M1.53 57.455,33.452 58.141,32.766 58.141,28.473 58.801,27.813 58.801,26.492 61.036,24.257 66.396,24.257 68.682,21.971 68.682,12.442 P4.12
RO: C8.1 M1.67 | length 5.4
  Top Layer w0.152: M1.67 40.8,38.227 40.8,39.301 C8.1
RX0: M1.37 P3.1 | length 34.4
  Top Layer w0.2: M1.37 v2(55.347,19.05)
  Bottom Layer w0.2: v2(55.347,19.05) 55.348,19.052 57.609,19.052 59.919,21.361 59.919,22.022 61.824,23.927 63.322,23.927 64.287,24.892 64.287,42.393 62.916,43.764 P3.1
RX5: M1.39 P4.9 | length 15.1
  Top Layer w0.15: M1.39 54.002,20.852 57.914,20.852 60.02,18.745 60.02,14.707 62.887,11.84 P4.9
RX+: C13.2 J3.3 | length 2.5
  Top Layer w0.15: J3.3 17.495,37.14 C13.2
RX-: C14.2 J3.6 | length 4
  Top Layer w0.15: J3.6 14.435,37.965 15.265,37.135 C14.2
RXI_N: C12.1 M1.85 R9.1 | length 8.2
  Top Layer w0.15: C12.1 R9.1 18.72,35.179 19.025,34.874 19.025,33.579 19.406,33.198 19.888,33.198 20.142,33.452 M1.85 M1.85
RXI_P: C11.1 M1.86 R10.1 | length 9.5
  Top Layer w0.15: C11.1 R10.1 20.523,34.214 24.587,34.214 25.248,33.553 25.248,32.842 24.955,32.55 M1.86
SDC0-CLK: J6.5 R3.2 | length 36.6
  Top Layer w0.254: J6.5 7.667,14.507 12.649,9.525 15.748,9.525 18.821,6.452 32.436,6.452 33.833,7.849 R3.2
SDC0-CMD: J6.3 M1.14 R28.2 | length 42.7
  Top Layer w0.2: J6.3 8.47,12.307 11.938,8.839 15.316,8.839 18.364,5.791 34.366,5.791 R28.2 37.2,8.625 M1.14@37.2,13
SDC0-D0: J6.7 M1.11 | length 40.2
  Top Layer w0.2: J6.7 2.739,16.696 8.069,16.696 12.065,12.7 13.792,12.7 19.304,7.188 32.156,7.188 34.5,9.532 M1.11@34.5,13
SDC0-D1: J6.8 M1.10 | length 39.2
  Top Layer w0.2: J6.8 2.739,17.746 8.112,17.746 12.497,13.36 13.894,13.36 19.482,7.772 31.877,7.772 33.6,9.495 M1.10@33.6,13
SDC0-D2: J6.1 M1.16 | length 44.6
  Top Layer w0.2: J6.1 7.978,10.107 13.564,4.521 34.798,4.521 39,8.723 M1.16@39,13
SDC0-D3: J6.2 M1.15 | length 43.7
  Top Layer w0.2: J6.2 8.427,11.207 11.303,8.331 14.961,8.331 18.11,5.182 34.646,5.182 38.1,8.636 M1.15@38.1,13
SDC0-DET: J6.G6 M1.17 R30.2 | length 38.8
  Top Layer w0.2: J6.G6 12.525,3.835 34.976,3.835 R30.2 39.903,12.997 M1.17
SPI1-CLK: M1.42 P4.3 | length 10.7
  Top Layer w0.15: M1.42 54.002,23.552 57.627,23.552 61.718,19.46 P4.3
SPI1-CS0: M1.41 P4.5 | length 11.8
  Top Layer w0.15: M1.41 M1.41 57.968,22.652 61.417,19.202 61.417,18.503 P4.5
SPI1-CS1: M1.45 P4.6 | length 20.7
  Top Layer w0.15: M1.45 54.002,26.252 57.695,26.252 60.935,23.012 66.015,23.012 67.259,21.768 67.259,18.639 P4.6
SPI1-MISO: M1.44 P4.2 | length 13.8
  Top Layer w0.15: M1.44 M1.44 57.3,25.352 61.697,20.955 64.495,20.955 P4.2
SPI1-MOSI: M1.43 P4.4 | length 13.6
  Top Layer w0.15: M1.43 54.002,24.452 57.336,24.452 61.214,20.574 64.426,20.574 P4.4
TX0: M1.36 P3.2 | length 38.4
  Top Layer w0.2: M1.36 v2(55.332,18.15)
  Bottom Layer w0.2: v2(55.332,18.15) 55.334,18.152 57.42,18.152 60.427,21.158 60.427,21.861 61.73,23.165 63.424,23.165 64.948,24.689 64.948,43.053 63.297,44.704 63.297,45.923 P3.2
TX5: M1.38 P4.11 | length 16.8
  Top Layer w0.15: M1.38 M1.38 58.179,19.952 59.538,18.593 59.538,12.762 P4.11
TX+: C11.2 J3.1 | length 2.5
  Top Layer w0.15: J3.1 19.535,37.158 C11.2
TX-: C12.2 J3.2 | length 2.5
  Top Layer w0.15: J3.2 18.517,39.589 C12.2
TXO_N: C14.1 M1.87 R1.1 | length 11.2
  Top Layer w0.15: C14.1 R1.1 16.967,34.671 16.967,33.122 v1(17.348,32.741) ; v1(18.593,32.741) 19.986,31.348 23.698,31.348 M1.87
  Bottom Layer w0.15: v1(17.348,32.741) v1(18.593,32.741)
TXO_P: C13.1 M1.88 R8.1 | length 10.6
  Top Layer w0.15: C13.1 R8.1 18.009,34.671 18.009,32.664 19.615,31.058 23.692,31.058 M1.88
USB0_N: J1.A7 J1.B7 M1.61 | length 10.1
  Top Layer w0.15: J1.A7 45.777,42.139 ; M1.61 45.908,35.292 45.908,38.347 45.777,38.478 45.777,42.139 ; J1.B7 46.777,42.306 46.609,42.139 45.777,42.139
USB0_P: J1.A6 J1.B6 M1.62 | length 11.1
  Top Layer w0.15: M1.62 45.618,35.318 45.618,38.227 45.487,38.358 45.487,41.94 45.277,42.15 J1.B6 45.277,43.88 45.441,44.044 46.101,44.044 46.277,43.868 J1.A6
USB1_N: M1.55 P1.2 | length 13
  Top Layer w0.117: M1.55 51.292,35.308 51.292,38.382 52.57,39.659 P1.2@60.25,39.659
USB1_P: M1.56 P1.3 | length 16.4
  Top Layer w0.117: M1.56 51.029,35.329 51.029,38.481 52.476,39.929 59.385,39.929 59.741,40.284 60.528,40.284 61.036,39.776 61.036,39.096 P1.3@60.25,38.309
USB2_N: M1.58 P2.2 | length 18.5
  Top Layer w0.15: M1.58 48.598,34.698 48.598,33.753 49.04,33.31 52.31,33.31 54.179,35.179 58.42,35.179 59.538,34.061 59.538,30.337 P2.2
USB2_P: M1.59 P2.3 | length 19.9
  Top Layer w0.15: M1.59 48.308,34.692 48.308,33.633 48.92,33.02 52.476,33.02 54.331,34.874 58.191,34.874 59.233,33.833 59.233,29.292 P2.3
VCC3V3: C5.2 C9.1 C16.1 D1.A J6.4 R5.1 R15.2 R16.2 R18.1 R20.1 R21.1 R22.1 R23.1 R24.1 R28.1 R30.1 U1.2 U1.4 U3.22 | length 165.4
  Top Layer w0.127: 3.226,21.133 4.15,21.133
  Top Layer w0.152: R18.1 R20.1 R21.1 R22.1
  Top Layer w0.2: R16.2 3.226,21.133 ; 4.15,21.133 R18.1 ; R22.1 7.302,20.13 7.849,19.583 8.636,19.583 9.1,20.047 R23.1 R24.1 11.074,20.676 11.989,21.59 C5.2 ; C5.2@12.701,21.591 U3.22
  Top Layer w0.3: J6.4 1.757,13.407 1.194,13.97 C9.1 v1(1.981,20.676) R16.2 ; v1(11.151,35.585) R5.1 ; v1(15.037,29.312) 15.037,27.051 16.281,25.806 R15.2
  Top Layer w0.43: v1(36.068,8.763) R28.1 ; v1(39.141,7.087) R30.1
  Top Layer w0.5: v1(24.397,41.314) D1.A
  Top Layer w0.6: D1.A 25.197,44.348 27.102,46.253 55.067,46.253 ; U1.4 58.035,47.934 C16.1
  Top Layer w1: U1.2 55.067,46.253 U1.4
  Bottom Layer w0.3: v1(15.037,29.312) 15.037,35.585
  Bottom Layer w0.43: v1(1.981,20.676) 1.981,16.739 9.957,8.763 v1(36.068,8.763) 37.465,8.763 v1(39.141,7.087)
  Bottom Layer w0.6: v1(1.981,20.676) 1.981,32.08 5.486,35.585 v1(11.151,35.585) 15.037,35.585 19.787,35.585 24.397,40.196 v1(24.397,41.314)
VCC_WIFI: C3.2 C4.2 R16.1 U3.9 | length 6.4
  Top Layer w0.305: U3.9 2.595,25.908 C4.2 C3.2 1.778,24.232 1.778,22.581 R16.1
VCCIN: C15.1 C17.1 C18.1 C19.1 C79.1 D2.A J1.A4 J1.A9 J1.B4 J1.B9 M1.49 M1.50 P1.1 P2.1 U1.3 | length 58.5
  Top Layer w0.3: v1(38.825,44.387) D2.A
  Top Layer w0.4: v1(42.647,41.199) C79.1 43.727,41.517 J1.B4 ; J1.A4@48.627,43.651 J1.A4 48.641,43.075 C15.1 v1(49.505,41.199)
  Top Layer w0.5: U1.3 59.334,42.134 C17.1
  Top Layer w0.6: M1.50 M1.49 v2(55.148,29.85) v2(55.965,29.85)
  Top Layer w0.7: 59.334,41.891 P1.1
  Top Layer w1: 59.334,41.891 59.334,42.134
  Bottom Layer w0.5: v1(38.825,44.387) 42.013,41.199 v1(42.647,41.199) ; C19.1 60.25,30.911 P2.1 60.25,35.102 59.08,36.271 59.08,39.805 P1.1 60.295,40.975 C18.1
  Bottom Layer w0.6: v2(55.148,29.85) 56.782,29.85 57.683,30.752 59.022,30.752 59.245,30.975 P2.1
  Bottom Layer w1: v1(42.647,41.199) v1(49.505,41.199) 60.026,41.199 P1.1
WL-REG-ON: M1.99 R18.2 R19.2 U3.12 | length 25.2
  Top Layer w0.15: v1(3.701,23.945) U3.12 3.701,21.598 R19.2 R18.2 ; v2(22.958,20.85) M1.99
  Bottom Layer w0.15: v1(3.701,23.945) 4.115,24.359 13.284,24.359 16.791,20.852 v2@22.958,20.852
WL-WAKE-AP: M1.95 U3.13 | length 22.2
  Top Layer w0.127: U3.13 4.601,24.133 v1(6.731,26.264)
  Top Layer w0.15: v2(22.911,24.45) M1.95
  Bottom Layer w0.127: v1(6.731,26.264) 15.24,26.264 17.052,24.452 v2@22.911,24.452
pads on no net: J1.A8 J1.B8 J3. J3.4 J3.5 J3.7 J3.8 J4.17 M1.6 M1.7 M1.8 M1.9 M1.48 M1.65 M1.91 M1.92 M1.93 M1.94 P1.7 P2.7 U3.4 U3.5 U3.8 U3.10 U3.11 U3.21 U3.23 U3.25 U3.26 U3.27 U3.28 U3.29 U3.32 U3.35 U3.37 U3.38 U3.39 U3.40

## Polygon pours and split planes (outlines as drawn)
GND on Top Layer "GND_L01_P000" (solid, remove dead copper, pour order 0): 0,0 70.002,0 70.002,50 0,50
GND on Bottom Layer "GND_L02_P001" (solid, remove dead copper, pour order 1): 0,0 70.002,0 70.002,50 0,50

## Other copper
Top Layer:
  pour cut-out: 1.889,38.447 1.889,37.967 1.833,37.911 1.651,37.911 1.651,38.391 1.595,38.447

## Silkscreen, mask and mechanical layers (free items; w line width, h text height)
Top Overlay:
  text "T" at 62.992,48.666 h1.27
  text "R" at 63.043,44.374 h1.27
  text "GND" at 59.004,21.654 h1.27
  text "MISO" at 67.056,21.629 h1.27
  text "CLK" at 58.915,19.1 h1.27
  text "MOSI" at 67.188,19.098 h1.27
  text "CUT OFF" at 29.693,17.729 h1
  text "CS0" at 59.059,16.564 h1.27
  text "CS1" at 67.332,16.562 h1.27
  text "PH10" at 67.208,14.161 h1.27
  text "PH4" at 58.908,14.106 h1.27
  text "RX5" at 59.052,11.584 h1.27
  text "PWR" at 67.315,11.465 h1.27
  text "RST" at 67.459,8.942 h1.27
  text "TX5" at 58.908,8.862 h1.27
  text "M-Core Demo" at 19.964,8.276 h2
  text "GND" at 59.106,7.151 h1.27
  text "1" at 39.675,6.934 h1.27
  text "3" at 41.846,6.941 h1.27
  text "5" at 44.906,6.947 h1.27
  text "7" at 47.414,6.941 h1.27
  text "9" at 50.012,6.941 h1.27
  text "11" at 52.045,6.934 h1.27
  text "15" at 57.226,6.947 h1.27
  text "13" at 54.61,6.923 h1.27
  text "20230108" at 19.934,6.168 h2
  text "PI" at 61.976,3.531 h2.03
  text "0" at 39.649,0.597 h1.27
  text "2" at 42.251,0.591 h1.27
  text "4" at 44.893,0.592 h1.27
  text "6" at 47.408,0.597 h1.27
  text "8" at 50.011,0.597 h1.27
  text "10" at 51.967,0.597 h1.27
  text "12" at 54.614,0.591 h1.27
  text "14" at 57.231,0.591 h1.27
  text "16" at 59.763,0.597 h1.27
Top Solder:
  circle w1.6: c66.5,3.5 r2.1
  circle w1.6: c66.5,46.5 r2.1
  circle w1.6: c3.5,46.5 r2.1
  circle w1.6: c3.5,3.5 r2.1
Bottom Solder:
  circle w1.6: c3.5,3.5 r2.1
  circle w1.6: c66.5,3.5 r2.1
  circle w1.6: c66.5,46.5 r2.1
  circle w1.6: c3.5,46.5 r2.1
Mechanical 1:
  circle w0.127: c66.5,46.5 r1.375
  circle w0.127: c66.5,3.5 r1.375
  circle w0.127: c3.5,46.5 r1.375
  circle w0.127: c3.5,3.5 r1.375
  lines w0.1: 9.165,50 9.165,41.89 22.765,41.89 22.765,50
  lines w0.127: 9.165,50 0,50 0,0 70.002,0 70.002,50 22.765,50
